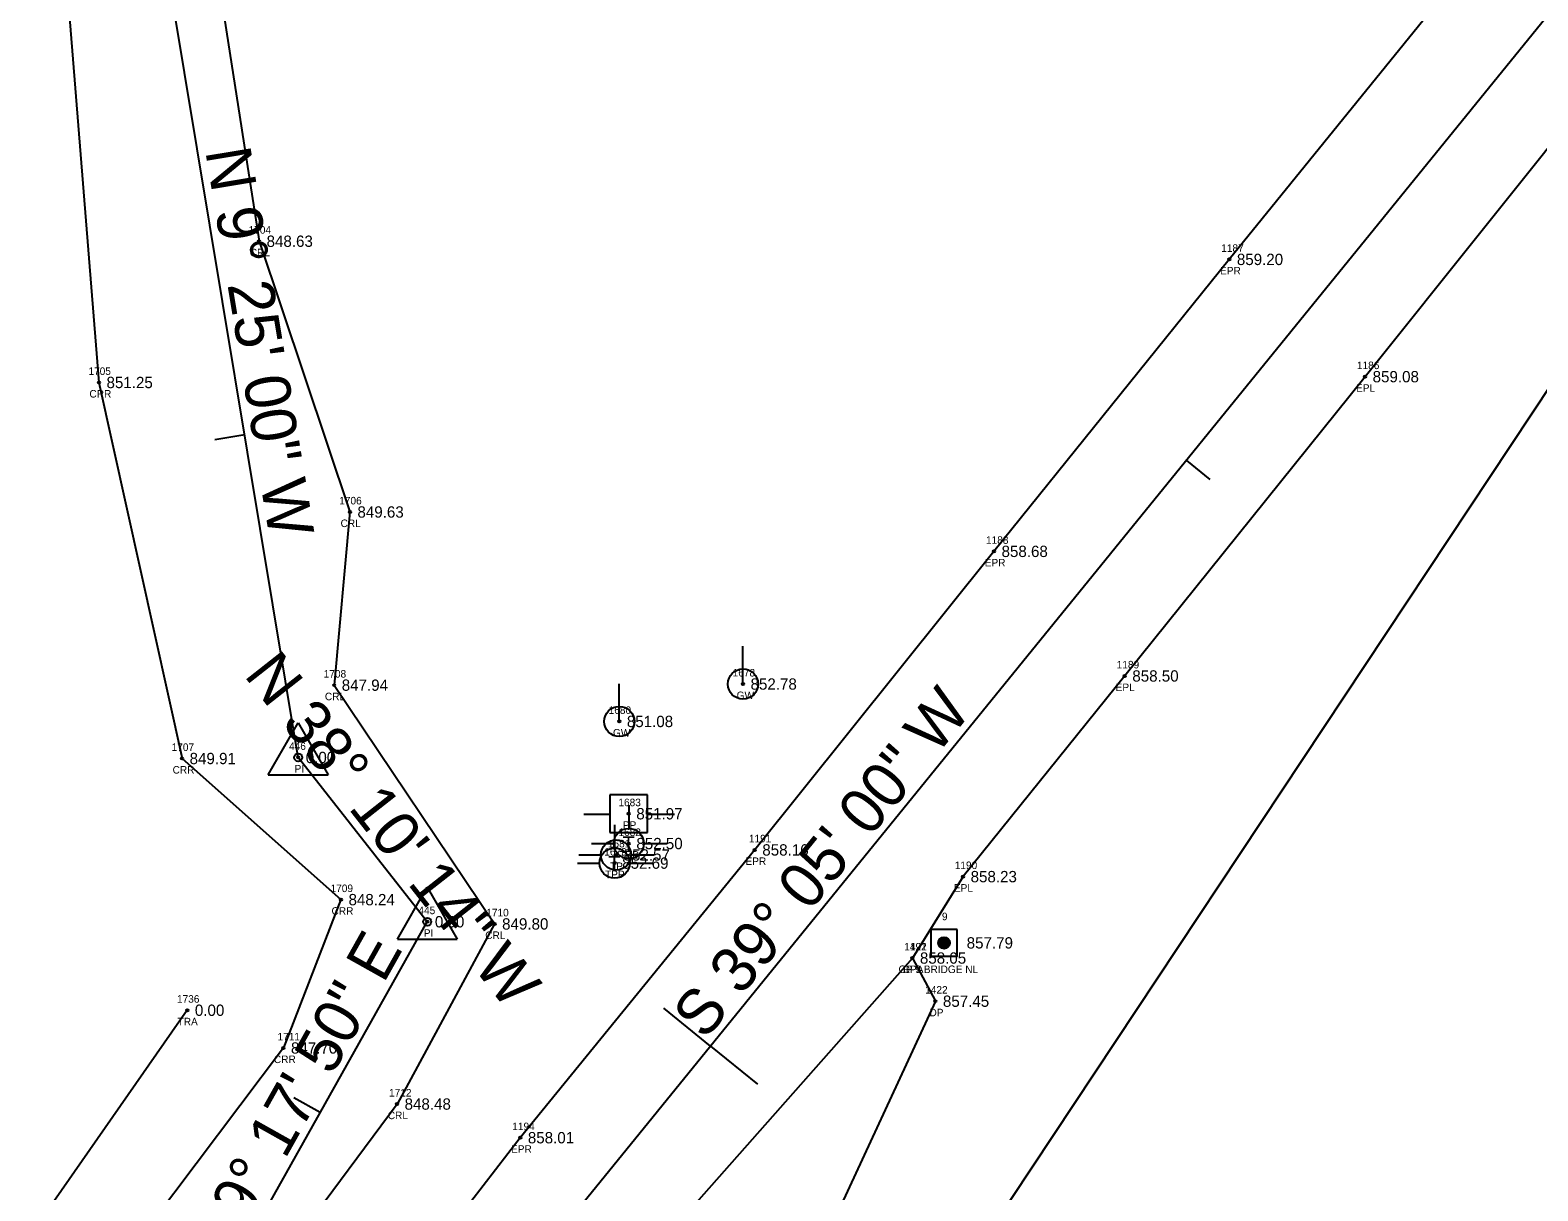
# Model space of a CAD drawing. Extents: x 1448136 to 1453623, y 1125056 to 1128842.
# Drawn here: x 1450680.5 to 1450880.3, y 1126992.5 to 1127146.3 of the extents above; entities that cross this region are included whole.
import ezdxf

# ---------------------------------------------------------------- set-up
doc = ezdxf.new("R2010")
doc.units = 0
for name, color, linetype in [('RD_EX_Driveway', 7, 'Continuous'), ('RD_EX_Driveway_txCode', 7, 'Continuous'), ('RD_EX_H2O', 7, 'Continuous'), ('RD_EX_H2O_txCode', 7, 'Continuous'), ('RD_EX_Road', 7, 'Continuous'), ('RD_EX_Road_txCode', 7, 'Continuous'), ('RD_EX_TX_Driveway_ELEV', 7, 'Continuous'), ('RD_EX_TX_H2O_ELEV', 7, 'Continuous'), ('RD_EX_TX_Road_ELEV', 7, 'Continuous'), ('RD_EX_TX_UT_ELEV', 7, 'Continuous'), ('RD_EX_TX_VEG_ELEV', 7, 'Continuous'), ('RD_EX_UT', 7, 'Continuous'), ('RD_EX_UT_txCode', 7, 'Continuous'), ('RD_EX_VEG', 7, 'Continuous'), ('RD_EX_VEG_txCode', 7, 'Continuous'), ('RD_HC_Cl', 7, 'Continuous'), ('RD_HC_Data', 7, 'Continuous'), ('RD_HC_Data_Tic', 7, 'Continuous'), ('RD_HC_Survey', 7, 'Continuous'), ('RD_HC_Survey_ELEV', 7, 'Continuous'), ('RD_HC_Survey_txCode', 7, 'Continuous'), ('RD_HC_txCode', 7, 'Continuous'), ('RD_SMD_Locator', 7, 'Continuous')]:
    doc.layers.add(name, color=color, linetype=linetype)

msp = doc.modelspace()

# ---------------------------------------------------------------- linework, layer by layer
at = {"layer": 'RD_EX_Driveway'}
msp.add_lwpolyline([(1450797.4, 1127023.38), (1450800.45, 1127017.66), (1450786.03, 1126986.46), (1450772.94, 1126979.75), (1450762.34, 1126983.69)], dxfattribs=at)
at = {"layer": 'RD_EX_H2O'}
for points in [[(1450790.27, 1127617.48), (1450787.4, 1127572.49), (1450770.56, 1127562.94), (1450759.96, 1127503.29), (1450769.34, 1127461.3), (1450745.95, 1127442.74), (1450719.19, 1127377.13), (1450706.09, 1127312.95), (1450685.57, 1127238.74), (1450684.42, 1127163.98), (1450689.62, 1127099.65), (1450700.63, 1127049.82), (1450721.69, 1127031.12), (1450714.06, 1127011.46), (1450690.92, 1126980.72), (1450694.81, 1126968.04), (1450702.96, 1126957.21), (1450718.26, 1126921.7)], [(1451186.93, 1127499.9), (1451179.17, 1127493.97), (1451140.72, 1127490.62), (1451106.63, 1127492.29), (1451048.45, 1127510.08), (1451003.54, 1127518.51), (1450913.12, 1127519.76), (1450847.92, 1127518.31), (1450803.27, 1127536.05), (1450784.14, 1127535.39), (1450799.36, 1127449.25), (1450771.54, 1127417.41), (1450741.81, 1127369.63), (1450735.37, 1127299.02), (1450712.28, 1127225.28), (1450704.18, 1127161.12), (1450710.83, 1127118.37), (1450722.87, 1127082.49), (1450720.79, 1127059.54), (1450742.04, 1127027.9), (1450729.12, 1127004.03), (1450716.3, 1126986.69), (1450718, 1126972.34), (1450745.7, 1126955.23)]]:
    msp.add_lwpolyline(points, dxfattribs=at)
at = {"layer": 'RD_EX_Road'}
for points in [[(1450902.69, 1127193.1), (1450871.02, 1127154.79), (1450870.72, 1127154.63), (1450839.4, 1127115.96), (1450808.22, 1127077.27), (1450776.52, 1127037.71), (1450745.45, 1126999.57), (1450734, 1126984.72)], [(1450889.12, 1127140.05), (1450857.39, 1127100.42), (1450825.55, 1127060.76), (1450804.12, 1127034.17), (1450797.4, 1127023.38), (1450762.34, 1126983.69), (1450751.57, 1126970.4)]]:
    msp.add_lwpolyline(points, dxfattribs=at)
at = {"layer": 'RD_EX_UT'}
for p, q in [((1450774.96, 1127059.69), (1450774.96, 1127064.69)), ((1450758.57, 1127054.73), (1450758.57, 1127059.73)), ((1450762.31, 1127045.01), (1450757.31, 1127045.01)), ((1450757.31, 1127045.01), (1450757.31, 1127040.01)), ((1450762.31, 1127040.01), (1450762.31, 1127045.01)), ((1450753.88, 1127042.45), (1450757.35, 1127042.45)), ((1450759.83, 1127043.62), (1450759.83, 1127040.55)), ((1450762.24, 1127042.45), (1450765.88, 1127042.45)), ((1450757.95, 1127041.03), (1450757.95, 1127037.96)), ((1450754.9, 1127038.56), (1450757.83, 1127038.56)), ((1450757.31, 1127040.01), (1450762.31, 1127040.01)), ((1450761.83, 1127038.56), (1450764.9, 1127038.56)), ((1450753.21, 1127037.06), (1450756.14, 1127037.06)), ((1450760.14, 1127037.06), (1450763.21, 1127037.06)), ((1450753.02, 1127035.97), (1450755.95, 1127035.97)), ((1450759.95, 1127035.97), (1450763.02, 1127035.97))]:
    msp.add_line(p, q, dxfattribs=at)
for centre in [(1450774.96, 1127059.69), (1450758.57, 1127054.73), (1450759.83, 1127038.55), (1450758.14, 1127037.04), (1450757.95, 1127035.96)]:
    msp.add_circle(centre, 2, dxfattribs=at)
at = {"layer": 'RD_EX_VEG'}
for points in [[(1451989.54, 1126836.98), (1451893.84, 1126905.64), (1451857.37, 1126942.27), (1451815.22, 1126966.53), (1451772.51, 1126993.52), (1451734.11, 1127020.41), (1451632.2, 1127074.86), (1451559.17, 1127115.62), (1451479.78, 1127184.41), (1451388.57, 1127251.26), (1451326.32, 1127287.16), (1451271.86, 1127300.71), (1451149.57, 1127304.55), (1451077.69, 1127285.44), (1451030.08, 1127262.15), (1450963.08, 1127198.6), (1450901.46, 1127121.24), (1450895.95, 1127120.38), (1450805.01, 1126983.22), (1450785.34, 1126934.46), (1450777.85, 1126863.1)], [(1450701.33, 1127016.46), (1450648.98, 1126941.43), (1450624.05, 1126912.28), (1450597.04, 1126871.16), (1450572.2, 1126846.23), (1450510.88, 1126885.49)]]:
    msp.add_lwpolyline(points, dxfattribs=at)
at = {"layer": 'RD_HC_Cl'}
for p, q in [((1450930.04, 1127207.93), (1450648.85, 1126861.73)), ((1450716.02, 1127049.96), (1450698.28, 1127156.94)), ((1450733.13, 1127028.19), (1450716.02, 1127049.96)), ((1450702.68, 1126973.92), (1450733.13, 1127028.19))]:
    msp.add_line(p, q, dxfattribs=at)
at = {"layer": 'RD_HC_Data'}
for p, q in [((1450712.05, 1127047.67), (1450716.02, 1127054.55)), ((1450716.02, 1127054.55), (1450719.99, 1127047.67)), ((1450712.05, 1127047.67), (1450719.99, 1127047.67)), ((1450729.16, 1127025.9), (1450733.13, 1127032.78)), ((1450733.13, 1127032.78), (1450737.1, 1127025.9)), ((1450729.16, 1127025.9), (1450737.1, 1127025.9))]:
    msp.add_line(p, q, dxfattribs=at)
for centre in [(1450716.02, 1127049.96), (1450733.13, 1127028.19)]:
    msp.add_circle(centre, 0.529, dxfattribs=at)
at = {"layer": 'RD_HC_Data_Tic'}
for p, q in [((1450708.93, 1127092.7), (1450704.98, 1127092.05)), ((1450833.71, 1127089.32), (1450836.81, 1127086.8)), ((1450770.66, 1127011.7), (1450764.45, 1127016.74)), ((1450770.66, 1127011.7), (1450776.87, 1127006.66)), ((1450718.94, 1127002.91), (1450715.46, 1127004.87))]:
    msp.add_line(p, q, dxfattribs=at)
at = {"layer": 'RD_HC_Survey'}
for p, q in [((1450800.85, 1127025.21), (1450800.85, 1127025.57)), ((1450800.88, 1127025.13), (1450800.88, 1127025.65)), ((1450800.9, 1127025.07), (1450800.9, 1127025.71)), ((1450800.92, 1127025.02), (1450800.92, 1127025.76)), ((1450800.95, 1127024.98), (1450800.95, 1127025.8)), ((1450800.97, 1127024.94), (1450800.97, 1127025.84)), ((1450801, 1127024.91), (1450801, 1127025.87)), ((1450801.02, 1127024.88), (1450801.02, 1127025.9)), ((1450801.05, 1127024.85), (1450801.05, 1127025.93)), ((1450801.07, 1127024.83), (1450801.07, 1127025.95)), ((1450801.1, 1127024.81), (1450801.1, 1127025.97)), ((1450801.12, 1127024.79), (1450801.12, 1127025.99)), ((1450801.15, 1127024.77), (1450801.15, 1127026.01)), ((1450801.17, 1127024.75), (1450801.17, 1127026.03)), ((1450801.2, 1127024.73), (1450801.2, 1127026.05)), ((1450801.22, 1127024.72), (1450801.22, 1127026.06)), ((1450801.25, 1127024.71), (1450801.25, 1127026.07)), ((1450801.27, 1127024.69), (1450801.27, 1127026.09)), ((1450801.3, 1127024.68), (1450801.3, 1127026.1)), ((1450801.32, 1127024.67), (1450801.32, 1127026.11)), ((1450801.35, 1127024.66), (1450801.35, 1127026.12)), ((1450801.37, 1127024.66), (1450801.37, 1127026.12)), ((1450801.39, 1127024.65), (1450801.39, 1127026.13)), ((1450801.42, 1127024.64), (1450801.42, 1127026.14)), ((1450801.44, 1127024.64), (1450801.44, 1127026.14)), ((1450801.47, 1127024.63), (1450801.47, 1127026.15)), ((1450801.49, 1127024.63), (1450801.49, 1127026.15)), ((1450801.52, 1127024.62), (1450801.52, 1127026.16)), ((1450801.54, 1127024.62), (1450801.54, 1127026.16)), ((1450801.57, 1127024.62), (1450801.57, 1127026.16)), ((1450801.59, 1127024.62), (1450801.59, 1127026.16)), ((1450801.62, 1127024.62), (1450801.62, 1127026.16)), ((1450801.64, 1127024.62), (1450801.64, 1127026.16)), ((1450801.67, 1127024.62), (1450801.67, 1127026.16)), ((1450801.69, 1127024.63), (1450801.69, 1127026.15)), ((1450801.72, 1127024.63), (1450801.72, 1127026.15)), ((1450801.74, 1127024.63), (1450801.74, 1127026.15)), ((1450801.77, 1127024.64), (1450801.77, 1127026.14)), ((1450801.79, 1127024.64), (1450801.79, 1127026.14)), ((1450801.82, 1127024.65), (1450801.82, 1127026.13)), ((1450801.84, 1127024.66), (1450801.84, 1127026.12)), ((1450801.86, 1127024.67), (1450801.86, 1127026.11)), ((1450801.89, 1127024.68), (1450801.89, 1127026.1)), ((1450801.91, 1127024.69), (1450801.91, 1127026.09)), ((1450801.94, 1127024.7), (1450801.94, 1127026.08)), ((1450801.96, 1127024.71), (1450801.96, 1127026.07)), ((1450801.99, 1127024.73), (1450801.99, 1127026.05)), ((1450802.01, 1127024.74), (1450802.01, 1127026.04)), ((1450802.04, 1127024.76), (1450802.04, 1127026.02)), ((1450802.06, 1127024.78), (1450802.06, 1127026)), ((1450802.09, 1127024.8), (1450802.09, 1127025.98)), ((1450802.11, 1127024.82), (1450802.11, 1127025.96)), ((1450802.14, 1127024.84), (1450802.14, 1127025.94)), ((1450802.16, 1127024.87), (1450802.16, 1127025.91)), ((1450802.19, 1127024.89), (1450802.19, 1127025.89)), ((1450802.21, 1127024.92), (1450802.21, 1127025.86)), ((1450802.24, 1127024.96), (1450802.24, 1127025.82)), ((1450802.26, 1127025), (1450802.26, 1127025.78)), ((1450802.29, 1127025.04), (1450802.29, 1127025.74)), ((1450802.31, 1127025.1), (1450802.31, 1127025.68)), ((1450802.34, 1127025.17), (1450802.34, 1127025.61)), ((1450802.36, 1127025.28), (1450802.36, 1127025.5))]:
    msp.add_line(p, q, dxfattribs=at)
msp.add_lwpolyline([(1450803.35, 1127027.14), (1450799.85, 1127027.14), (1450799.85, 1127023.64), (1450803.35, 1127023.64)], close=True, dxfattribs=at)
msp.add_circle((1450801.6, 1127025.39), 0.769, dxfattribs=at)
at = {"layer": 'RD_SMD_Locator'}
for centre in [(1450710.83, 1127118.37), (1450839.4, 1127115.96), (1450857.39, 1127100.42), (1450689.62, 1127099.65), (1450722.87, 1127082.49), (1450808.22, 1127077.27), (1450825.55, 1127060.76), (1450720.79, 1127059.54), (1450774.96, 1127059.69), (1450758.57, 1127054.73), (1450700.63, 1127049.82), (1450716.02, 1127049.96), (1450759.82, 1127042.5), (1450759.83, 1127038.55), (1450758.14, 1127037.04), (1450776.52, 1127037.71), (1450757.95, 1127035.96), (1450804.12, 1127034.17), (1450721.69, 1127031.12), (1450733.13, 1127028.19), (1450742.04, 1127027.9), (1450801.6, 1127025.39), (1450797.4, 1127023.38), (1450797.4, 1127023.38), (1450701.33, 1127016.46), (1450800.45, 1127017.66), (1450714.06, 1127011.46), (1450729.12, 1127004.03), (1450745.45, 1126999.57)]:
    msp.add_circle(centre, 0.15, dxfattribs=at)

# ---------------------------------------------------------------- texts
at = {"layer": 'RD_EX_Driveway_txCode'}
for s, p in [('1421', (1450796.33, 1127024.38)), ('DPA', (1450796.13, 1127021.38)), ('1422', (1450799.1, 1127018.66)), ('DP', (1450799.67, 1127015.66))]:
    msp.add_text(s, height=1, dxfattribs=at).set_placement(p)
at = {"layer": 'RD_EX_H2O_txCode'}
for s, p in [('1704', (1450709.45, 1127119.37)), ('CRL', (1450709.6, 1127116.37)), ('1705', (1450688.23, 1127100.65)), ('CRR', (1450688.36, 1127097.65)), ('1706', (1450721.46, 1127083.49)), ('CRL', (1450721.64, 1127080.49)), ('1708', (1450719.4, 1127060.54)), ('CRL', (1450719.56, 1127057.54)), ('1707', (1450699.25, 1127050.82)), ('CRR', (1450699.38, 1127047.82)), ('1709', (1450720.31, 1127032.12)), ('CRR', (1450720.44, 1127029.12)), ('1710', (1450740.94, 1127028.9)), ('CRL', (1450740.81, 1127025.9)), ('1711', (1450713.28, 1127012.46)), ('CRR', (1450712.8, 1127009.46)), ('1712', (1450728.06, 1127005.03)), ('CRL', (1450727.89, 1127002.03))]:
    msp.add_text(s, height=1, dxfattribs=at).set_placement(p)
at = {"layer": 'RD_EX_Road_txCode'}
for s, p in [('1187', (1450838.33, 1127116.96)), ('EPR', (1450838.17, 1127113.96)), ('1186', (1450856.31, 1127101.42)), ('EPL', (1450856.19, 1127098.42)), ('1188', (1450807.16, 1127078.27)), ('EPR', (1450806.99, 1127075.27)), ('1189', (1450824.48, 1127061.76)), ('EPL', (1450824.34, 1127058.76)), ('1191', (1450775.74, 1127038.71)), ('EPR', (1450775.29, 1127035.71)), ('1190', (1450803.02, 1127035.17)), ('EPL', (1450802.91, 1127032.17)), ('1192', (1450796.33, 1127024.38)), ('EPL', (1450796.19, 1127021.38)), ('1194', (1450744.39, 1127000.57)), ('EPR', (1450744.22, 1126997.57))]:
    msp.add_text(s, height=1, dxfattribs=at).set_placement(p)
at = {"layer": 'RD_EX_TX_Driveway_ELEV'}
for s, p in [('858.05', (1450798.4, 1127022.63)), ('857.45', (1450801.45, 1127016.91))]:
    msp.add_text(s, height=1.5, dxfattribs=at).set_placement(p)
at = {"layer": 'RD_EX_TX_H2O_ELEV'}
for s, p in [('848.63', (1450711.83, 1127117.62)), ('851.25', (1450690.62, 1127098.9)), ('849.63', (1450723.87, 1127081.74)), ('847.94', (1450721.79, 1127058.79)), ('849.91', (1450701.63, 1127049.07)), ('848.24', (1450722.69, 1127030.37)), ('849.80', (1450743.04, 1127027.15)), ('847.70', (1450715.06, 1127010.71)), ('848.48', (1450730.12, 1127003.28))]:
    msp.add_text(s, height=1.5, dxfattribs=at).set_placement(p)
at = {"layer": 'RD_EX_TX_Road_ELEV'}
for s, p in [('859.20', (1450840.4, 1127115.21)), ('859.08', (1450858.39, 1127099.67)), ('858.68', (1450809.22, 1127076.52)), ('858.50', (1450826.55, 1127060.01)), ('858.16', (1450777.52, 1127036.96)), ('858.23', (1450805.12, 1127033.42)), ('858.05', (1450798.4, 1127022.63)), ('858.01', (1450746.45, 1126998.82))]:
    msp.add_text(s, height=1.5, dxfattribs=at).set_placement(p)
at = {"layer": 'RD_EX_TX_UT_ELEV'}
for s, p in [('852.78', (1450775.96, 1127058.94)), ('851.08', (1450759.57, 1127053.98)), ('852.50', (1450760.83, 1127037.8)), ('852.69', (1450758.95, 1127035.21)), ('852.57', (1450759.14, 1127036.29))]:
    msp.add_text(s, height=1.5, dxfattribs=at).set_placement(p)
at = {"layer": 'RD_EX_TX_VEG_ELEV'}
msp.add_text('0.00', height=1.5, dxfattribs=at).set_placement((1450702.33, 1127015.71))
at = {"layer": 'RD_EX_UT'}
for p in [(1450758.98, 1127037.5), (1450757.1, 1127034.91)]:
    msp.add_text('T', height=2, dxfattribs=at).set_placement(p)
at = {"layer": 'RD_EX_UT_txCode'}
for s, p in [('1678', (1450773.59, 1127060.69)), ('GW', (1450774.12, 1127057.69)), ('1680', (1450757.16, 1127055.73)), ('GW', (1450757.73, 1127052.73)), ('1683', (1450758.45, 1127043.5)), ('1682', (1450758.46, 1127039.55)), ('PP', (1450759.04, 1127040.5)), ('1681', (1450757.05, 1127038.04)), ('1679', (1450756.58, 1127036.96)), ('TPP', (1450758.56, 1127036.55)), ('TPP', (1450756.68, 1127033.96)), ('TP', (1450757.35, 1127035.04))]:
    msp.add_text(s, height=1, dxfattribs=at).set_placement(p)
at = {"layer": 'RD_EX_VEG_txCode'}
for s, p in [('1736', (1450699.96, 1127017.46)), ('TRA', (1450700.04, 1127014.46))]:
    msp.add_text(s, height=1, dxfattribs=at).set_placement(p)
at = {"layer": 'RD_HC_Data'}
for s, rotation, p in [('N 9%%d 25\' 00" W', 279.4166, (1450703.7, 1127130.34)), ('N 38%%d 10\' 14" W', 308.1707, (1450708.73, 1127060.85)), ('S 39%%d 05\' 00" W', 50.9167, (1450769.92, 1127012.37)), ('N 29%%d 17\' 50" E', 60.7028, (1450703.31, 1126977.09))]:
    msp.add_text(s, height=6, rotation=rotation, dxfattribs=at).set_placement(p)
at = {"layer": 'RD_HC_Survey_ELEV'}
for s, p in [('0.00', (1450717.02, 1127049.21)), ('851.97', (1450760.82, 1127041.75)), ('0.00', (1450734.13, 1127027.44)), ('857.79', (1450804.6, 1127024.64))]:
    msp.add_text(s, height=1.5, dxfattribs=at).set_placement(p)
at = {"layer": 'RD_HC_Survey_txCode'}
for s, p in [('9', (1450801.32, 1127028.39)), ('CP 9 BRIDGE NL', (1450795.57, 1127021.39))]:
    msp.add_text(s, height=1, dxfattribs=at).set_placement(p)
at = {"layer": 'RD_HC_txCode'}
for s, p in [('446', (1450714.81, 1127050.96)), ('PI', (1450715.54, 1127047.96)), ('445', (1450731.95, 1127029.19)), ('PI', (1450732.66, 1127026.19))]:
    msp.add_text(s, height=1, dxfattribs=at).set_placement(p)

doc.saveas('drawing.dxf')
